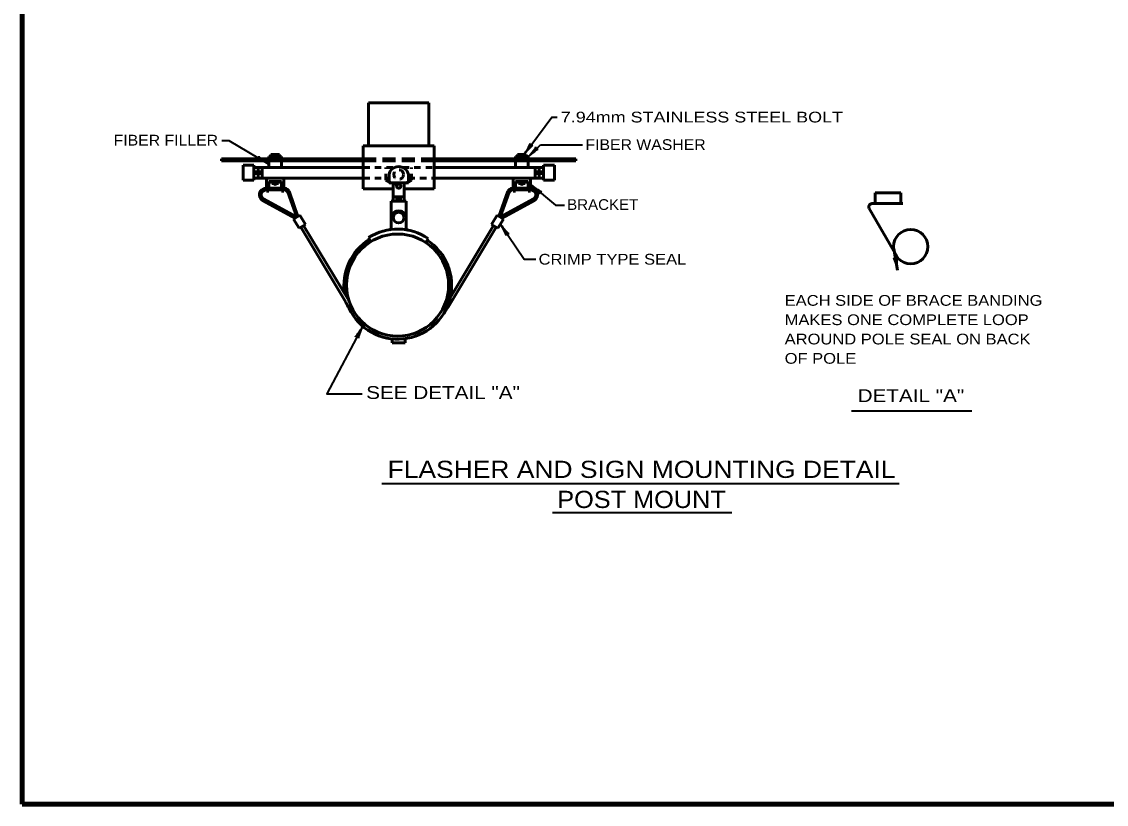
# Model space of a CAD drawing. Extents: x -31 to 825, y 0 to 544.
# Drawn here: x 26.3 to 329.4, y 11.8 to 230.5 of the extents above; entities that cross this region are included whole.
import ezdxf
from ezdxf.enums import TextEntityAlignment as Align

# ---------------------------------------------------------------- set-up
doc = ezdxf.new("R2010")
doc.units = 0
doc.header["$LTSCALE"] = 1.2
doc.linetypes.add('MEDIUM_DASHED', pattern=[4.5, 3, -1.5])
doc.linetypes.add('SHORT_DASHED', pattern=[2.7, 1.5, -1.2])
doc.layers.add('1', color=7, linetype='Continuous', lineweight=53)

msp = doc.modelspace()

# ---------------------------------------------------------------- linework, layer by layer
at = {"layer": '1'}
for p, q in [((123.259, 207.756), (140.059, 207.756)), ((123.259, 207.756), (123.259, 195.756)), ((140.059, 207.756), (140.059, 195.756)), ((121.759, 195.756), (141.559, 195.756)), ((121.759, 195.756), (121.759, 183.756)), ((141.559, 195.756), (141.559, 183.756)), ((121.759, 192.156), (82.159, 192.156)), ((82.159, 192.156), (82.159, 191.556)), ((121.759, 191.556), (82.159, 191.556)), ((95.359, 192.756), (95.359, 192.156)), ((95.359, 192.756), (98.959, 192.756)), ((95.359, 191.556), (95.359, 189.756)), ((95.959, 193.356), (95.959, 192.756)), ((95.959, 193.356), (98.359, 193.356)), ((97.159, 193.356), (97.159, 192.756)), ((98.359, 193.356), (98.359, 192.756)), ((98.959, 192.756), (98.959, 192.156)), ((98.959, 191.556), (98.959, 189.756)), ((141.559, 192.156), (181.159, 192.156)), ((141.559, 191.556), (181.159, 191.556)), ((164.26, 192.756), (164.26, 192.156)), ((167.86, 192.756), (164.26, 192.756)), ((164.26, 191.556), (164.26, 189.756)), ((164.86, 193.356), (164.86, 192.756)), ((167.26, 193.356), (164.86, 193.356)), ((166.06, 193.356), (166.06, 192.756)), ((167.26, 193.356), (167.26, 192.756)), ((167.86, 192.756), (167.86, 192.156)), ((167.86, 191.556), (167.86, 189.756)), ((181.159, 192.156), (181.159, 191.556)), ((88.159, 190.356), (88.159, 186.156)), ((88.159, 190.356), (91.159, 190.356)), ((91.159, 190.356), (91.159, 186.156)), ((121.759, 189.756), (91.159, 189.756)), ((91.759, 188.856), (91.759, 187.656)), ((92.359, 189.756), (92.359, 186.756)), ((92.959, 188.856), (92.959, 187.656)), ((93.559, 189.756), (93.559, 186.756)), ((141.559, 189.756), (172.159, 189.756)), ((169.759, 189.756), (169.759, 186.756)), ((170.359, 188.856), (170.359, 187.656)), ((170.959, 189.756), (170.959, 186.756)), ((171.559, 188.856), (171.559, 187.656)), ((172.159, 190.356), (172.159, 186.156)), ((172.159, 190.356), (175.159, 190.356)), ((175.159, 190.356), (175.159, 186.156)), ((88.159, 186.156), (91.159, 186.156)), ((121.759, 186.756), (91.159, 186.756)), ((94.759, 186.756), (94.759, 183.156)), ((95.359, 185.856), (95.359, 183.156)), ((95.359, 185.856), (98.959, 185.856)), ((96.259, 185.256), (96.259, 185.856)), ((96.259, 185.256), (98.059, 185.256)), ((98.059, 185.256), (98.059, 185.856)), ((98.959, 185.856), (98.959, 183.156)), ((99.559, 186.756), (99.559, 183.957)), ((128.959, 185.418), (128.959, 187.818)), ((128.959, 185.418), (134.359, 185.418)), ((130.159, 180.318), (130.159, 185.418)), ((133.159, 180.318), (133.159, 185.418)), ((134.359, 185.418), (134.359, 187.818)), ((141.559, 186.756), (172.159, 186.756)), ((163.66, 186.756), (163.66, 183.957)), ((164.26, 185.856), (164.26, 183.156)), ((167.86, 185.856), (164.26, 185.856)), ((165.18, 185.256), (165.18, 185.856)), ((166.98, 185.256), (165.18, 185.256)), ((166.98, 185.256), (166.98, 185.856)), ((167.86, 185.856), (167.86, 183.156)), ((168.46, 186.756), (168.46, 183.156)), ((175.159, 186.156), (172.159, 186.156)), ((94.459, 183.936), (94.759, 183.936)), ((94.459, 183.456), (94.759, 183.456)), ((94.759, 183.156), (95.359, 183.156)), ((95.359, 183.936), (98.959, 183.936)), ((95.359, 183.456), (98.959, 183.456)), ((98.959, 183.156), (99.559, 183.156)), ((99.559, 183.936), (99.859, 183.936)), ((99.559, 183.93), (99.559, 183.156)), ((99.559, 183.456), (99.859, 183.456)), ((100.672, 182.839), (103.157, 175.845)), ((101.024, 183.118), (103.527, 176.071)), ((121.759, 183.756), (130.159, 183.756)), ((133.159, 183.756), (141.559, 183.756)), ((162.195, 183.118), (159.692, 176.071)), ((162.546, 182.839), (160.061, 175.845)), ((163.66, 183.936), (163.36, 183.936)), ((163.66, 183.456), (163.36, 183.456)), ((163.66, 183.93), (163.66, 183.156)), ((164.26, 183.156), (163.66, 183.156)), ((167.86, 183.936), (164.26, 183.936)), ((167.86, 183.456), (164.26, 183.456)), ((168.46, 183.156), (167.86, 183.156)), ((168.76, 183.936), (168.46, 183.936)), ((264.772, 182.651), (271.972, 182.651)), ((264.772, 182.651), (264.772, 179.351)), ((271.972, 182.651), (271.972, 179.351)), ((93.499, 180.581), (102.7, 175.565)), ((93.796, 180.95), (103.157, 175.845)), ((129.559, 172.93), (129.559, 180.318)), ((129.559, 180.318), (133.759, 180.318)), ((130.159, 181.518), (133.159, 181.518)), ((130.759, 180.918), (132.559, 180.918)), ((133.759, 172.837), (133.759, 180.318)), ((169.423, 180.95), (160.061, 175.845)), ((169.719, 180.581), (160.519, 175.565)), ((264.172, 179.651), (272.572, 179.651)), ((104.023, 176.375), (102.291, 175.314)), ((104.023, 176.375), (105.59, 173.817)), ((159.196, 176.375), (157.628, 173.817)), ((159.196, 176.375), (160.927, 175.314)), ((270.91, 164.768), (263.11, 178.278)), ((102.291, 175.314), (103.859, 172.756)), ((105.59, 173.817), (103.859, 172.756)), ((116.89, 152.087), (104.291, 173.021)), ((117.876, 152.258), (105.087, 173.509)), ((145.774, 151.166), (158.928, 173.021)), ((146.096, 153.511), (158.132, 173.509)), ((157.628, 173.817), (159.36, 172.756)), ((160.927, 175.314), (159.36, 172.756)), ((123.274, 170.142), (123.918, 169.039)), ((139.895, 169.889), (139.24, 168.767)), ((270.003, 166.982), (271.045, 161.07)), ((129.859, 141.837), (129.859, 140.697)), ((129.859, 140.697), (133.459, 140.697)), ((133.459, 141.897), (133.459, 140.697))]:
    msp.add_line(p, q, dxfattribs=at)
at = {"layer": '1', "lineweight": 35}
for p, q in [((167.845, 192.748), (171.305, 196.052)), ((171.305, 196.052), (183.067, 196.052)), ((258.202, 121.78), (291.852, 121.78))]:
    msp.add_line(p, q, dxfattribs=at)
at = {"layer": '1', "linetype": 'MEDIUM_DASHED'}
for p, q in [((121.759, 192.156), (141.559, 192.156)), ((121.759, 191.556), (141.559, 191.556))]:
    msp.add_line(p, q, dxfattribs=at)
at = {"layer": '1', "linetype": 'SHORT_DASHED'}
for p, q in [((121.759, 189.756), (130.567, 189.756)), ((128.059, 186.156), (128.059, 189.756)), ((132.75, 189.756), (141.559, 189.756)), ((135.259, 186.156), (135.259, 189.756)), ((121.759, 186.756), (128.959, 186.756)), ((128.059, 186.156), (130.159, 185.118)), ((130.159, 185.118), (133.159, 185.118)), ((135.259, 186.156), (133.159, 185.118)), ((134.359, 186.756), (141.559, 186.756))]:
    msp.add_line(p, q, dxfattribs=at)
at = {"layer": '1', "lineweight": 40}
for p, q in [((126.933, 101.465), (271.539, 101.465)), ((174.602, 93.337), (224.712, 93.337))]:
    msp.add_line(p, q, dxfattribs=at)
at = {"layer": '1', "lineweight": 158}
msp.add_line((818.018, 11.803), (26.418, 11.803), dxfattribs=at)
msp.add_lwpolyline([(818.018, 537.903), (26.318, 537.803), (26.418, 11.803)], dxfattribs=at)
at = {"layer": '1', "lineweight": 35}
for points in [[(166.705, 193.39), (174.439, 203.785), (175.936, 203.785)], [(95.309, 190.704), (84.285, 197.213), (82.241, 197.213)], [(168.665, 184.869), (175.508, 179.236), (178.003, 179.236)], [(160.147, 173.888), (166.705, 164.119), (169.984, 164.119)], [(121.583, 145.294), (111.604, 126.469), (121.441, 126.469)]]:
    msp.add_lwpolyline(points, dxfattribs=at)
at = {"layer": '1', "linetype": 'SHORT_DASHED'}
msp.add_circle((131.654, 187.742), 1.35, dxfattribs=at)
at = {"layer": '1'}
for centre, radius in [((131.677, 184.538), 0.6), ((131.651, 175.726), 1.5), ((131.365, 156.88), 14.259), ((274.75, 167.618), 4.8)]:
    msp.add_circle(centre, radius, dxfattribs=at)
for centre, radius, start, end in [((131.659, 187.214), 2.767, 12.60158, 167.39842), ((97.159, 185.305), 0.304, 189.12521, 350.87479), ((166.08, 185.305), 0.304, 189.12521, 350.87479), ((94.594, 182.083), 1.858, 94.17839, 233.90406), ((94.626, 182.071), 1.395, 96.86656, 233.49849), ((99.523, 182.221), 1.748, 30.86815, 78.94071), ((99.686, 182.383), 1.087, 24.77948, 80.83321), ((163.695, 182.221), 1.748, 101.05929, 149.13185), ((163.533, 182.383), 1.087, 99.16679, 155.22052), ((168.624, 182.083), 1.858, 306.09594, 85.82161), ((168.593, 182.071), 1.395, 306.50151, 83.13344), ((263.984, 178.699), 0.971, 78.82629, 205.71781), ((131.659, 175.493), 2.125, 8.79741, 171.20259), ((128.959, 172.93), 0.6, 278.94897, 360), ((134.359, 172.837), 0.6, 180, 259.07917), ((131.393, 157.468), 15.052, 55.60897, 122.64417), ((131.41, 156.809), 15.052, 121.43132, 188.90095), ((131.41, 156.809), 15.052, 205.41262, 56.93176), ((157.54, 144.641), 13.8, 155.72513, 155.72513), ((129.882, 157.885), 14.227, 204.05208, 211.98432), ((88.016, 190.786), 70.041, 323.71745, 325.55127)]:
    msp.add_arc(centre, radius, start, end, dxfattribs=at)
at = {"layer": '1', "lineweight": 40}
for centre, major_axis, ratio, start_param, end_param in [((167.22, 194.638), (-1.129, -1.831), 0.122415, 0.8963533, 3.1415927), ((167.711, 194.317), (1.427, 1.565), 0.07063, 6.2823074, 8.5597026), ((168.563, 193.892), (-1.42, -1.615), 0.122415, 0.8963533, 3.1415927), ((168.993, 193.493), (1.67, 1.303), 0.07063, 6.2823074, 8.5597026), ((94.013, 191.084), (1.94, -0.928), 0.122415, 0.8963533, 3.1415927), ((94.013, 191.084), (1.94, -0.928), 0.122415, 0.8963533, 3.1415927), ((94.281, 191.606), (1.708, -1.253), 0.07063, 3.1407148, 5.41811), ((94.281, 191.606), (1.708, -1.253), 0.07063, 3.1407148, 5.41811), ((169.887, 184.292), (-1.774, 1.217), 0.122415, 0.8963533, 3.1415927), ((169.542, 183.818), (1.493, -1.502), 0.07063, 6.2823074, 8.5597026), ((160.686, 172.63), (1, -1.867), 0.07063, 6.2823074, 8.5597026), ((160.686, 172.63), (1, -1.867), 0.07063, 6.2823074, 8.5597026), ((161.152, 172.985), (-1.35, 1.675), 0.122415, 0.8963533, 3.1415927), ((161.152, 172.985), (-1.35, 1.675), 0.122415, 0.8963533, 3.1415927), ((270.491, 162.301), (0.557, -2.078), 0.122415, 0.8963533, 3.1415927), ((270.491, 162.301), (0.557, -2.078), 0.122415, 0.8963533, 3.1415927), ((271.062, 162.438), (0.158, -2.112), 0.07063, 3.1407148, 5.41811), ((271.062, 162.438), (0.158, -2.112), 0.07063, 3.1407148, 5.41811), ((120.729, 144.225), (-1.173, -1.764), 0.07063, 6.2823074, 8.5597026), ((121.263, 143.982), (0.838, 1.981), 0.122415, 0.8963533, 3.1415927)]:
    msp.add_ellipse(centre, major_axis=major_axis, ratio=ratio, start_param=start_param, end_param=end_param, dxfattribs=at)

# ---------------------------------------------------------------- texts
at = {"layer": '1'}
for s, height, width, p in [('7.94mm STAINLESS STEEL BOLT', 3, 1.25, (176.96, 202.312)), ('FIBER FILLER', 3, 1.1, (52.01, 195.864)), ('FIBER WASHER', 3, 1.1, (183.856, 194.625)), ('BRACKET', 3, 1.05, (178.733, 177.874)), ('CRIMP TYPE SEAL', 3, 1.15, (170.754, 162.6)), ('EACH SIDE OF BRACE BANDING', 3, 1.15, (239.516, 151.093)), ('MAKES ONE COMPLETE LOOP', 3, 1.15, (239.516, 145.693)), ('AROUND POLE SEAL ON BACK', 3, 1.15, (239.516, 140.293)), ('OF POLE', 3, 1.15, (239.516, 134.893)), ('SEE DETAIL "A"', 3.6, 1.2, (122.584, 125.056)), ('DETAIL "A"', 3.6, 1.2, (259.904, 124.187))]:
    msp.add_text(s, height=height, dxfattribs=dict(at, width=width)).set_placement(p)
for s, width, p in [('FLASHER AND SIGN MOUNTING DETAIL', 1.15, (199.52, 102.994)), ('POST MOUNT', 1.1, (199.52, 94.594))]:
    msp.add_text(s, height=4.8, dxfattribs=dict(at, width=width)).set_placement(p, align=Align.CENTER)

doc.saveas('drawing.dxf')
